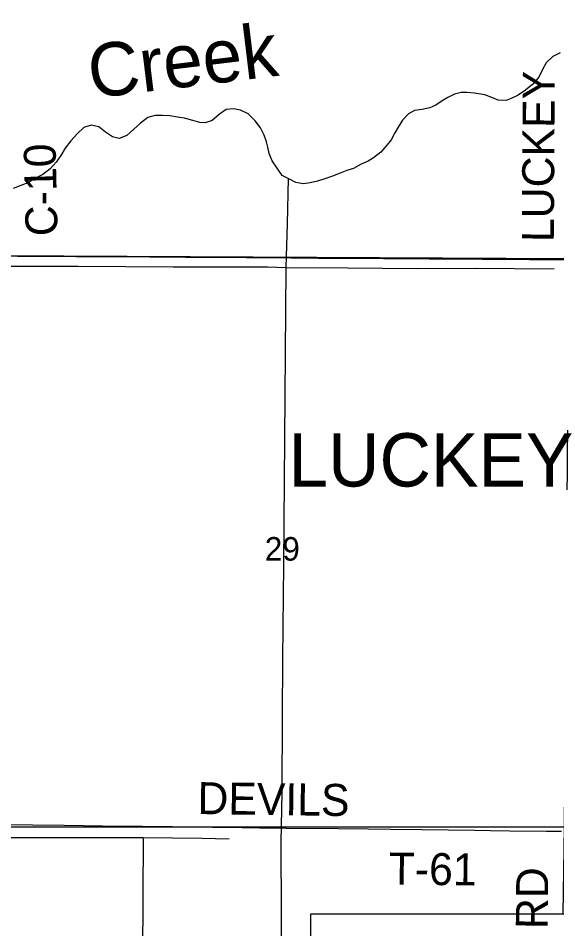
# Model space of a CAD drawing. Extents: x 0 to 34, y 0 to 22.
# Drawn here: x 2.522 to 3.48, y 16.867 to 18.485 of the extents above; entities that cross this region are included whole.
import ezdxf

# ---------------------------------------------------------------- set-up
doc = ezdxf.new("R2010")
doc.units = 0
for name, color, linetype in [('GM_X_Corporation_Text', 7, 'Continuous'), ('GM_X_County_Road_Text', 7, 'Continuous'), ('GM_X_Major_River', 7, 'Continuous'), ('GM_X_Major_River_Text', 7, 'Continuous'), ('GM_X_Minor_River', 7, 'Continuous'), ('GM_X_Section', 7, 'Continuous'), ('GM_X_Section_Text', 7, 'Continuous'), ('GM_X_State_Route', 7, 'Continuous'), ('GM_X_Township_Road', 7, 'Continuous'), ('GM_X_Township_Road_Text', 7, 'Continuous'), ('SH_Text', 7, 'Continuous')]:
    doc.layers.add(name, color=color, linetype=linetype)

msp = doc.modelspace()

# ---------------------------------------------------------------- linework, layer by layer
at = {"layer": 'GM_X_Major_River'}
for points in [[(3.4863, 18.4235), (3.4732, 18.417), (3.4612, 18.4055), (3.4549, 18.3939), (3.4481, 18.3797), (3.4379, 18.3678), (3.4244, 18.3571), (3.4117, 18.3479), (3.399, 18.3421), (3.3904, 18.3383), (3.3762, 18.3389), (3.3646, 18.3437), (3.3522, 18.3486), (3.3341, 18.3513), (3.3202, 18.3528), (3.3099, 18.3527), (3.2981, 18.3499), (3.2866, 18.3437), (3.2766, 18.3379), (3.2654, 18.3302), (3.2547, 18.3255), (3.241, 18.3228), (3.2273, 18.3205), (3.2166, 18.3147), (3.2061, 18.3035), (3.1982, 18.2912), (3.1923, 18.2811), (3.1855, 18.2688), (3.1781, 18.2591), (3.1676, 18.2468), (3.1544, 18.2365), (3.1448, 18.231), (3.1322, 18.2253), (3.1187, 18.218), (3.1071, 18.2143)], [(3.1071, 18.2143), (3.0948, 18.2093), (3.0811, 18.2042), (3.0677, 18.1991), (3.0547, 18.1952), (3.0418, 18.192), (3.0292, 18.1907), (3.0164, 18.1929), (3.0025, 18.2), (2.9919, 18.2055), (2.9831, 18.2182), (2.9742, 18.2313), (2.9687, 18.2444), (2.9663, 18.2558), (2.9638, 18.2653), (2.9599, 18.2772), (2.9533, 18.2899), (2.944, 18.3026), (2.9313, 18.3146), (2.9178, 18.3213), (2.9061, 18.3238), (2.8924, 18.3226), (2.8805, 18.3144), (2.8674, 18.3033), (2.8551, 18.299), (2.8457, 18.2992), (2.8328, 18.3032), (2.8185, 18.3069), (2.8056, 18.3087), (2.792, 18.3112), (2.7791, 18.3118), (2.7662, 18.3117), (2.7532, 18.3081), (2.7401, 18.2985), (2.7282, 18.2877), (2.7154, 18.2766), (2.7021, 18.2711), (2.69, 18.274), (2.678, 18.2822), (2.6656, 18.292), (2.6524, 18.2949), (2.639, 18.2906), (2.6278, 18.2798), (2.6158, 18.2671), (2.6061, 18.2536), (2.5983, 18.2408), (2.5901, 18.2288), (2.5793, 18.2174), (2.5665, 18.2072), (2.5535, 18.2006), (2.5397, 18.1921), (2.5271, 18.1874), (2.5133, 18.182)]]:
    msp.add_lwpolyline(points, dxfattribs=at)
at = {"layer": 'GM_X_Minor_River'}
for points in [[(3.0025, 18.2), (3.0007, 18.1194), (2.9984, 18.0416), (2.9959, 17.7375), (2.994, 17.5136), (2.9923, 17.3464), (2.9916, 17.2438), (2.9912, 17.1096), (2.9894, 17.0203), (2.99, 16.8918), (2.99, 16.7606), (2.9898, 16.6333), (2.9904, 16.4933), (2.9852, 16.3125), (2.9825, 16.1643), (2.9813, 16.0408)], [(2.4788, 18.0443), (2.6292, 18.0442), (2.7981, 18.0431), (2.9662, 18.0429), (2.9984, 18.0416), (3.1078, 18.0415)], [(3.1078, 18.0415), (3.2325, 18.0399), (3.3351, 18.0408), (3.4756, 18.0397)], [(2.1, 17.04), (2.1033, 17.04), (2.2406, 17.0361), (2.3642, 17.0318), (2.4454, 17.0298), (2.4761, 17.0289), (2.5638, 17.0291), (2.6591, 17.029), (2.7445, 17.0292), (2.8488, 17.0277), (2.8978, 17.0267)], [(2.7445, 17.0292), (2.7434, 16.819), (2.7411, 16.6982), (2.7389, 16.5808), (2.738, 16.4546), (2.736, 16.306), (2.7325, 16.1438), (2.7308, 16.0548)]]:
    msp.add_lwpolyline(points, dxfattribs=at)
at = {"layer": 'GM_X_Section'}
for points in [[(3.5044, 19.0749), (3.5019, 18.057), (2.4915, 18.0628), (2.4993, 19.0815)], [(3.5019, 18.057), (3.4934, 17.0475), (2.4879, 17.0483), (2.4915, 18.0628)]]:
    msp.add_lwpolyline(points, close=True, dxfattribs=at)
msp.add_lwpolyline([(3.4773, 16.1435), (3.4754, 16.0365), (3.4686, 16.0366), (2.4803, 16.0422), (2.4865, 16.4094), (2.4879, 17.0483), (3.4934, 17.0475), (3.4907, 16.8935)], dxfattribs=at)
at = {"layer": 'GM_X_State_Route'}
msp.add_lwpolyline([(2.1, 18.0629), (2.1654, 18.0625), (2.198, 18.0623), (2.2695, 18.0621), (2.313, 18.0623), (2.372, 18.0625), (2.4559, 18.0623), (2.4932, 18.0623), (2.5212, 18.0621), (2.6253, 18.0616), (2.6921, 18.0614), (2.8211, 18.0604), (2.9283, 18.0596), (3.0076, 18.059), (3.0558, 18.0585), (3.1024, 18.0582), (3.1723, 18.0579), (3.2531, 18.0572), (3.2826, 18.057), (3.3479, 18.0565), (3.4318, 18.0561), (3.4753, 18.0558), (3.4975, 18.0561)], dxfattribs=at)
at = {"layer": 'GM_X_Township_Road'}
msp.add_lwpolyline([(2.4899, 17.0522), (2.5014, 17.0521), (2.548, 17.0515), (2.604, 17.0508), (2.6723, 17.0498), (2.7438, 17.0491), (2.7966, 17.0484), (2.8526, 17.0478), (2.8681, 17.0476), (2.921, 17.047), (2.952, 17.0465), (2.9614, 17.0463), (2.9987, 17.0459), (3.0919, 17.0449), (3.1447, 17.0443), (3.1851, 17.0439), (3.2411, 17.0432), (3.3343, 17.0421), (3.3623, 17.0417), (3.3965, 17.0412), (3.4617, 17.0405), (3.4866, 17.0403), (3.4885, 17.0403)], dxfattribs=at)
at = {"layer": 'SH_Text'}
msp.add_lwpolyline([(3.0426, 16.8935), (5.0426, 16.8935), (5.0426, 16.1435), (3.0426, 16.1435)], close=True, dxfattribs=at)

# ---------------------------------------------------------------- texts
at = {"layer": 'GM_X_Corporation_Text'}
msp.add_text('LUCKEY', height=0.0947, rotation=0, dxfattribs=at).set_placement((3.0031, 17.6527))
at = {"layer": 'GM_X_County_Road_Text'}
for s, rotation, p in [('LUCKEY', 89.6626, (3.4749, 18.0869)), ('C-10', 91.3251, (2.5927, 18.098)), ('RD', 89.5045, (3.4641, 16.8662))]:
    msp.add_text(s, height=0.05682, rotation=rotation, dxfattribs=at).set_placement(p)
at = {"layer": 'GM_X_Major_River_Text'}
msp.add_text('Creek', height=0.09476, rotation=6.9145, dxfattribs=at).set_placement((2.6525, 18.3421))
at = {"layer": 'GM_X_Section_Text'}
msp.add_text('29', height=0.04186, rotation=0, dxfattribs=at).set_placement((2.961, 17.521))
at = {"layer": 'GM_X_Township_Road_Text'}
for s, rotation, p in [('DEVILS', 359.2281, (2.841, 17.0708)), ('T-61', 359.2931, (3.1811, 16.9457))]:
    msp.add_text(s, height=0.05682, rotation=rotation, dxfattribs=at).set_placement(p)

doc.saveas('drawing.dxf')
